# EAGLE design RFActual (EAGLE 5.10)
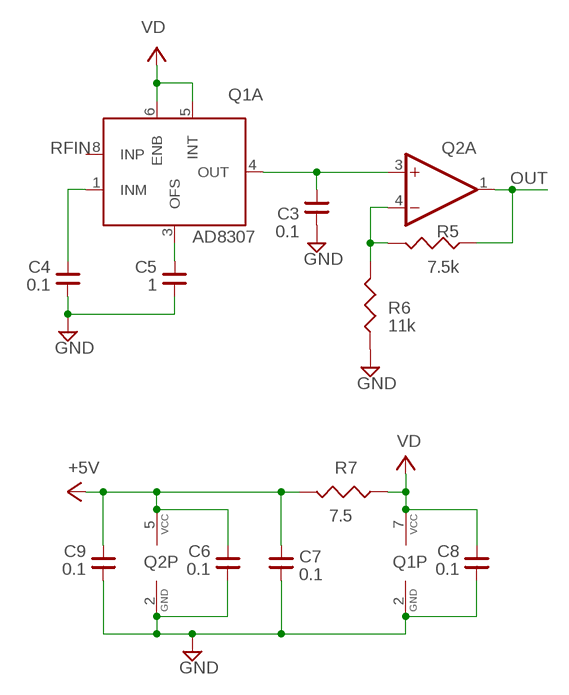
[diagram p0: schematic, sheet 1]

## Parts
C3  0.1  CAP-NPDC  [805C]
C4  0.1  CAP-NPDC  [805C]
C5  1  CAP-NPDC  [805C]
C6  0.1  CAP-NPDC  [805C]
C7  0.1  CAP-NPDC  [805C]
C8  0.1  CAP-NPDC  [805C]
C9  0.1  CAP-NPDC  [805C]
Q1  AD8307  [SO08]
Q2  OPAMP-SINGLE  [SOT23-5]
R5  7.5k  RESISTORC  [805C]
R6  11k  RESISTORC  [805C]
R7  7.5  RESISTORC  [805C]

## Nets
+3V3: C6.2 C7.2 C9.2 Q2.5(P:VCC) R7.2 ; supply symbol labelled +5V
GND: C3.1 C4.1 C5.1 C6.1 C7.1 C8.1 C9.1 Q1.2(P:GND) Q2.2(P:GND) R6.1
N$3: C4.2 Q1.1(A:INM)
N$5: C3.2 Q1.4(A:OUT) Q2.3(A:+IN)
N$6: Q2.4(A:-IN) R5.2 R6.2
N$7: C5.2 Q1.3(A:OFS)
OUT: Q2.1(A:OUT) R5.1
VD: C8.2 Q1.5(A:INT) Q1.6(A:ENB) Q1.7(P:VCC) R7.1
Unconnected: Q1.8(A:INP)

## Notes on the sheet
- RFIN
- OUT

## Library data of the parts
C3-C9 = agar:CAP-NP: Non-polarized capacitor
Q1 = agar:AD8307: DC-500MHz Log Detector
Q2 = agar:OPAMP-SINGLE
R5-R7 = agar:RESISTOR

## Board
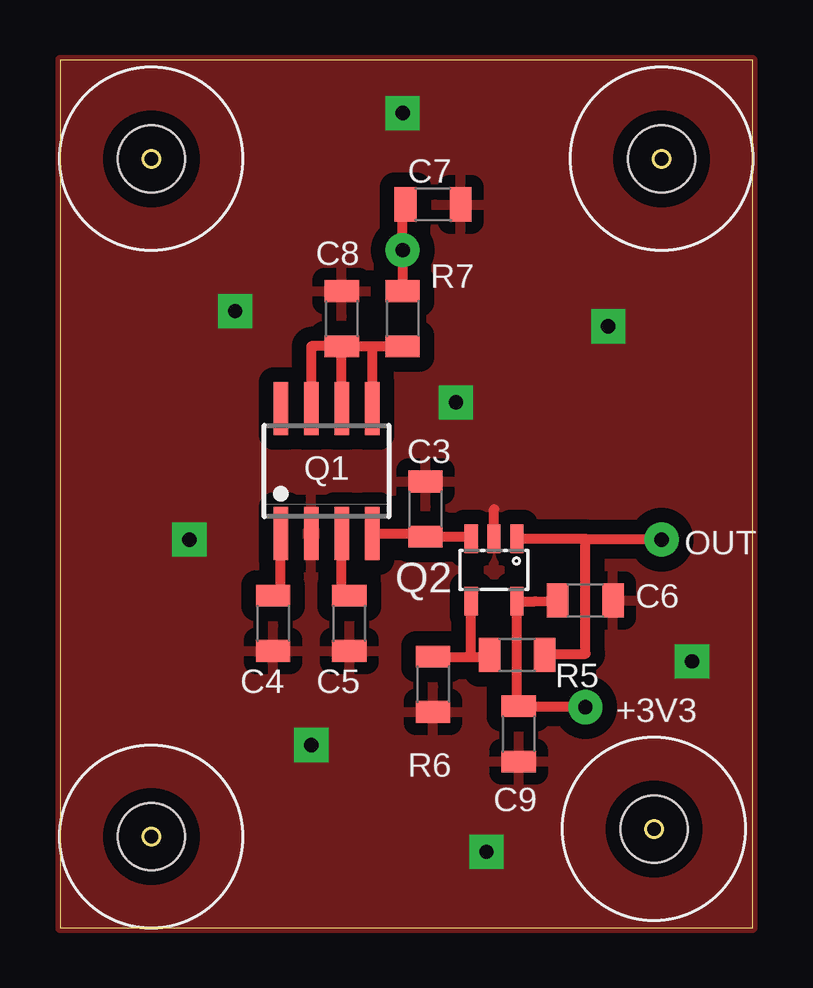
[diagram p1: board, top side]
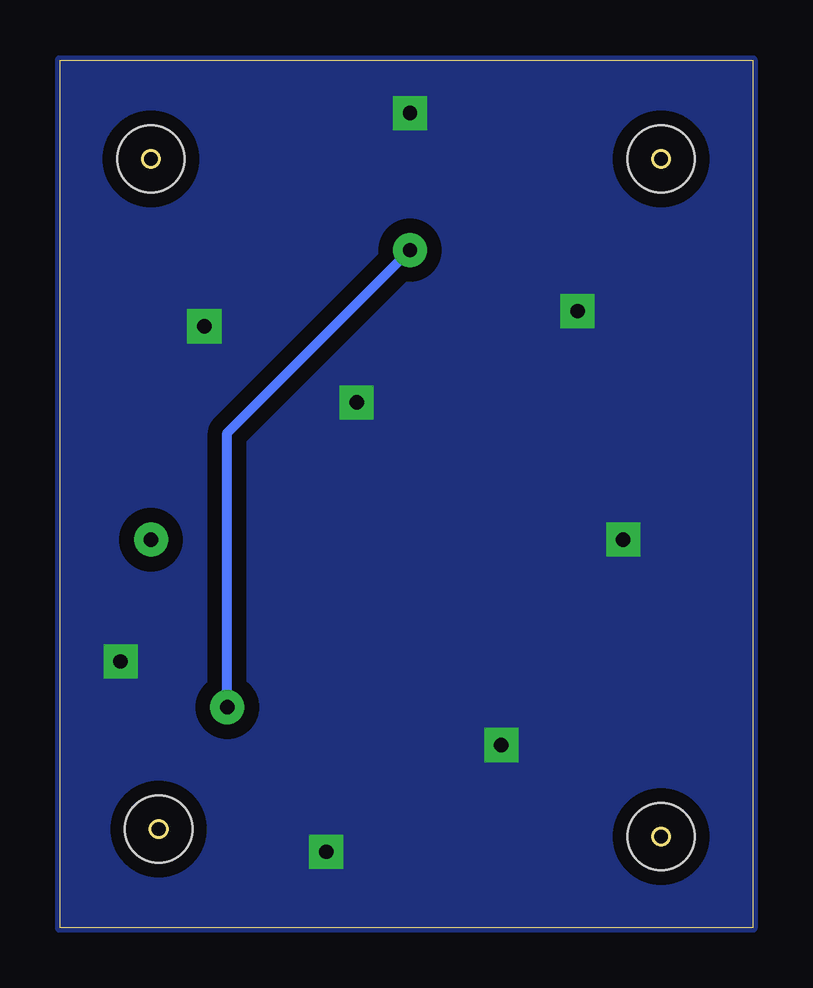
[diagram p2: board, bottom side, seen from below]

Size 28.88 x 36.19 mm. Coordinates in mm from the lower left corner, seen from the top.
Outline: 0,0 28.88,0 28.88,36.19 0,36.19 0,0
Copper layers (1*16): Top 0.035mm / dielectric 1.5mm / Bottom 0.035mm
Design rules "default *": minimum track width 10mil, minimum drill 24mil, track to track 8mil, track to pad 8mil, pad to pad 8mil, via to via 8mil, smd to smd 8mil, copper to edge 0mil, drill to drill 8mil, minimum pad ring 10mil, minimum via ring 8mil, stop-mask expansion 4mil, vias tented up to drill 0mil, thermal gap 20mil

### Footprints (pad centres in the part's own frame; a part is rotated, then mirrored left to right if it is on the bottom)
805C = smd 0.9 x 1.422: 1 -1.15,0; 2 1.15,0
SO08 = smd 0.6 x 2.2: 1 -1.905,-2.6; 2 -0.635,-2.6; 3 0.635,-2.6; 4 1.905,-2.6; 5 1.905,2.6; 6 0.635,2.6; 7 -0.635,2.6; 8 -1.905,2.6
SOT23-5 = smd 0.55 x 1.2: 1 -0.95,-1.3; 2 0,-1.3; 3 0.95,-1.3; 4 0.95,1.3; 5 -0.95,1.3
MOUNTING-HOLE-PLAIN = hole 2.8: 0,0

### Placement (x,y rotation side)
C3  15.24,17.46 270 top
C4  8.89,12.7 90 top
C5  12.06,12.7 90 top
C6  21.91,13.65 180 top
C7  15.56,30.16 180 top
C8  11.75,25.4 270 top
C9  19.13,8.09 90 top
Q1  11.11,19.05 0 top
Q2  18.1,14.92 180 top
R5  19.06,11.38 180 top
R6  15.56,10.16 90 top
R7  14.29,25.4 90 top
U$1  [MOUNTING-HOLE-PLAIN]  3.81,3.81 0 top
U$2  [MOUNTING-HOLE-PLAIN]  3.81,32.07 0 top
U$3  [MOUNTING-HOLE-PLAIN]  25.08,32.07 0 top
U$4  [MOUNTING-HOLE-PLAIN]  24.77,4.13 0 top

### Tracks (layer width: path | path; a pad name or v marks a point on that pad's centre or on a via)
+3V3  (via drill 0.6 pad 1.42)
  Top 0.406: v21.91,9.21 21.91,9.24 C9.2 19.05,9.24 Q2.5 19.8,13.62 C6.2 | R7.2 v14.29,28.26 14.29,30.16 C7.2
  Bottom 0.406: v14.29,28.26 21.91,20.64 v21.91,9.21
GND  (via drill 0.6 pad 1.42)
  Top 0.406: Q2.2 18.1,17.46
  other vias: 17.78,3.17 26.35,11.11 5.4,16.19 16.51,21.91 10.48,7.62 22.86,25.08 7.3,25.72 14.29,33.97
  pour Bottom (isolate 0.61): 0,0 28.88,0 28.88,36.19 0,36.19
  pour Top (isolate 0.61): 0,0 28.88,0 28.88,36.19 0,36.19
  pour Bottom (isolate 0.61): 0,0 28.88,0 28.88,36.19 0,36.19
N$3
  Top 0.406: C4.2 9.21,13.85 Q1.1
N$5
  Top 0.406: Q1.4 15.1,16.45 C3.2 17.06,16.31 Q2.3
N$6
  Top 0.406: R6.2 17.14,11.31 | 17.14,11.31 17.91,11.31 R5.2 | Q2.4 17.14,11.31
N$7
  Top 0.406: C5.2 11.75,13.85 Q1.3
OUT  (via drill 0.6 pad 1.42)
  Top 0.406: 21.91,16.22 Q2.1 | 21.91,16.22 21.91,11.43 20.21,11.43 R5.1 | 21.91,16.22 25.08,16.22 v25.08,16.19
VD
  Top 0.406: Q1.6 C8.2 | C8.2 10.48,24.25 Q1.7 | C8.2 13.02,24.25 | 13.02,24.25 R7.1 | 13.02,24.25 Q1.5

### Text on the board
tNames: OUT | +3V3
